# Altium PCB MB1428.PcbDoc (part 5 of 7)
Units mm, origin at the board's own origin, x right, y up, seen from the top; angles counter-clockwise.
Board outline 55.88 x 152.4 mm, 4 copper layers (Top Layer, Signal Layer 1, Signal Layer 2, Bottom Layer), stack 1.614 mm thick; 396 components, 227 nets, 1346 pads, 1469 vias.
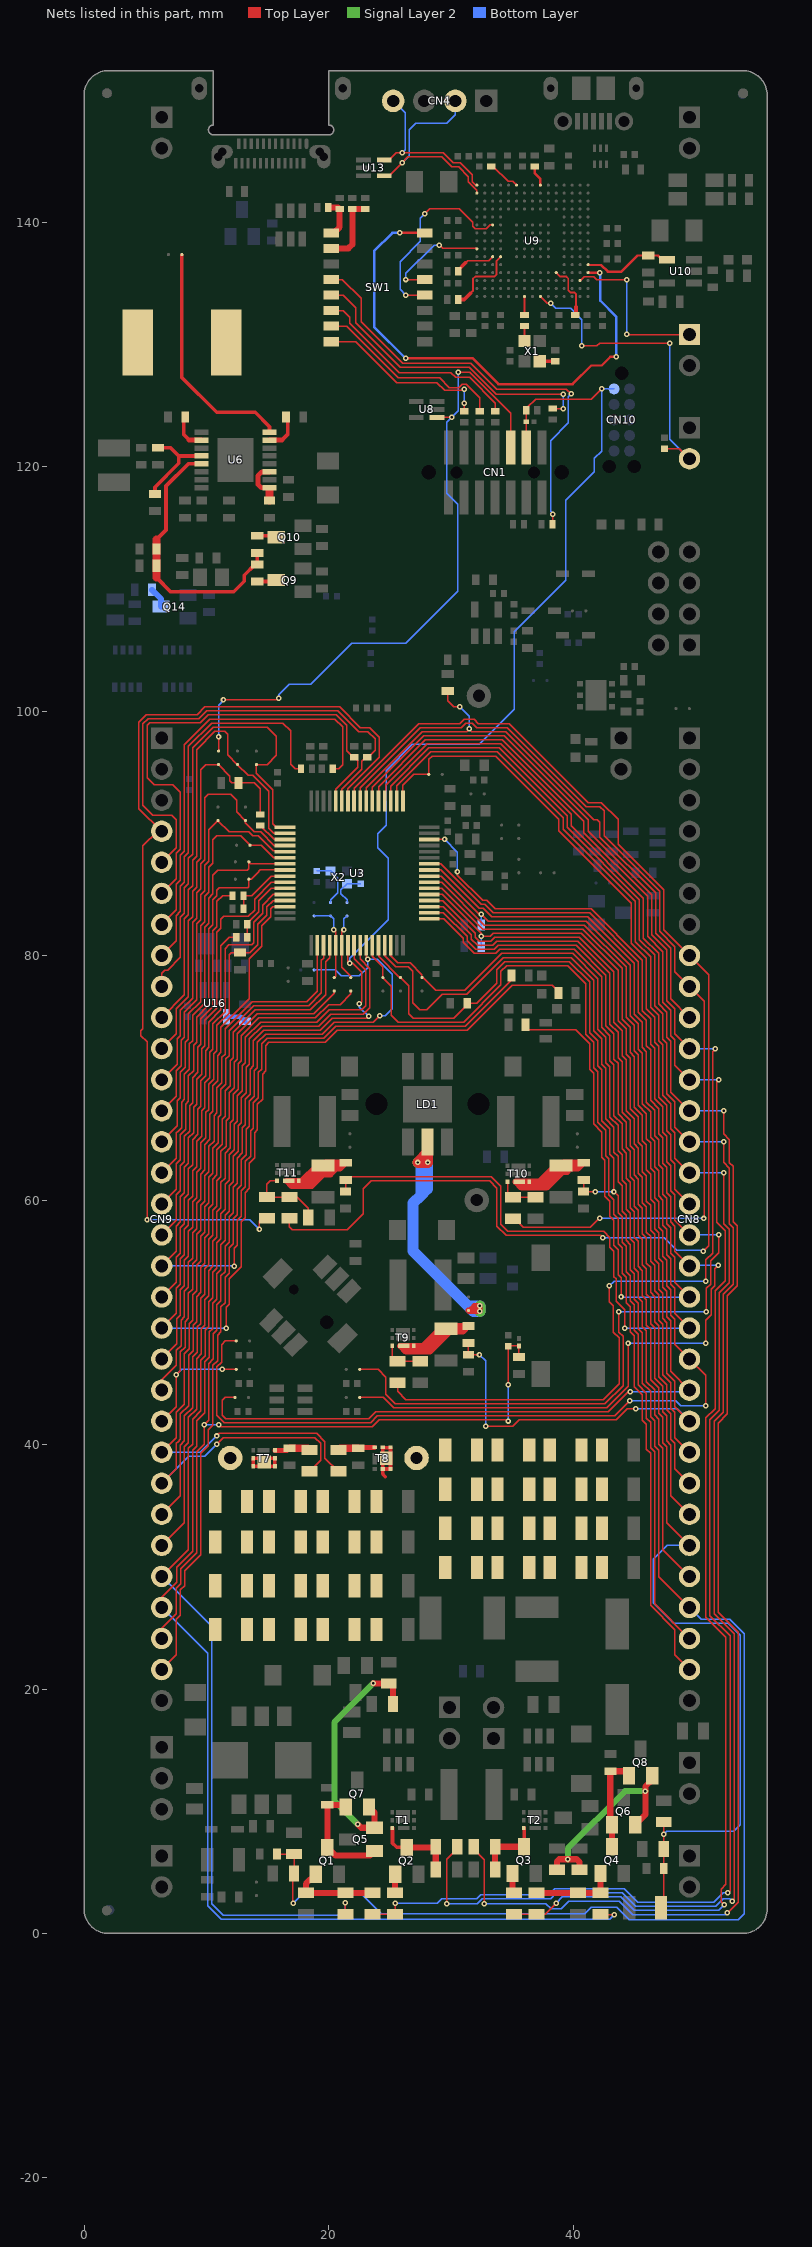
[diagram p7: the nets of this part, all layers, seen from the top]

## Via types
v1: diameter 0.45, hole 0.2, Top Layer to Bottom Layer, tented both sides, 1460 vias
v2: diameter 0.6, hole 0.2, Top Layer to Bottom Layer, tented both sides, 9 vias

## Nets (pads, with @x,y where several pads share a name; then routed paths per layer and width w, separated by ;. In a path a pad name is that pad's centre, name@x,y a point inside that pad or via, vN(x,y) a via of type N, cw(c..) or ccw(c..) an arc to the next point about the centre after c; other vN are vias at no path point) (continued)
NetQ1_1: Q1.1 R1.2 R2.2 R3.2 | length 7.3
  Top Layer w0.5: Q1.1@18.95,4.85 18.15,4.05 R1.2@18.15,3.325 R2.2@21.375,3.325 R3.2@23.6,3.325
NetQ1_3: Q1.3 Q5.1 Q7.1 R23.1 | length 9.3
  Top Layer w0.5: Q7.1@21.4,10.35 21.225,10.525 R23.1@19.9,10.525 Q1.3@19.9,7.05 20.575,6.375 23.375,6.375 Q5.1@23.75,6.75
NetQ2_1: Q2.1 R4.2 | length 1.5
  Top Layer w0.5: R4.2@25.45,3.325 Q2.1@25.45,4.85
NetQ2_3: Q2.3 R12.2 R19.2 T1.3 | length 6.8
  Top Layer w0.3: T1.3@25.238,8.625 25.238,7.387 25.575,7.05 Q2.3@26.4,7.05
  Top Layer w0.5: Q2.3@26.4,7.05 28.725,7.05 R19.2@28.775,7.1 R12.2@28.775,5.25
NetQ3_1: Q3.1 R5.1 | length 1.6
  Top Layer w0.5: Q3.1@35.05,4.9 35.05,3.45 R5.1@35.175,3.325
NetQ3_3: Q3.3 R13.2 R20.1 T2.3 | length 5.7
  Top Layer w0.3: Q3.3@36,7.1 T2.3@36,8.625
  Top Layer w0.5: R13.2@33.625,5.25 R20.1@33.625,7.1 Q3.3@36,7.1
NetQ4_1: Q4.1 R6.1 R7.2 R8.1 | length 6.8
  Top Layer w0.5: R6.1@37.025,3.325 R7.2@40.4,3.325 R8.1@42.25,3.325 Q4.1@42.25,4.9
NetQ4_3: Q4.3 Q6.1 Q8.1 R26.1 | length 7.9
  Top Layer w0.5: Q4.3@43.2,7.1 Q6.1@43.2,8.9 43.05,9.05 43.05,13.25 R26.1@43.075,13.275 44.2,13.275 Q8.1@44.575,12.9
NetQ5_2: Q5.2 Q7.2 R27.1 R28.1 | length 20.1
  Top Layer w0.5: v1(22.4,8.925) 22.675,8.65 Q5.2@23.75,8.65 23.75,9.9 Q7.2@23.3,10.35 ; v1(23.675,20.475) 23.7,20.45 R28.1@24.925,20.45 25.275,20.1 R27.1@25.275,18.775
  Signal Layer 2 w0.5: v1(22.4,8.925) 20.475,10.85 20.475,17.275 v1(23.675,20.475)
NetQ6_2: Q6.2 Q8.2 R14.2 R15.2 | length 17.1
  Top Layer w0.5: R14.2@38.675,5.2 38.675,5.875 38.875,6.075 v1(39.588,6.075) 40.3,6.075 40.525,5.85 R15.2@40.525,5.2 ; Q6.2@45.1,8.9 45.925,9.725 v1(45.925,11.65) 45.925,12.025 46.475,12.575 Q8.2@46.475,12.9
  Signal Layer 2 w0.5: v1(39.588,6.075) 39.588,6.962 44.275,11.65 v1(45.925,11.65)
NetQ9_3: Q9.3 R99.1 | length 1.6
  Top Layer w0.3: R99.1@14.175,110.6 15.6,110.6 Q9.3@15.725,110.725
NetQ10_3: Q10.3 R102.1 | length 1.6
  Top Layer w0.3: R102.1@14.175,114.35 15.6,114.35 Q10.3@15.725,114.225
NetQ14_3: Q14.3 R142.1 | length 1.7
  Bottom Layer w0.5: R142.1@5.55,109.925 6.3,109.175 Q14.3@6.3,108.55
NetR29_1: R29.1 R33.1 R41.1 R49.1 T7.1 T7.2 T7.5 T7.6 T7.8 TP1.1 | length 4.8
  Top Layer w0.3: T7.6@13.85,38.225 15.6,38.225 15.6,38.875 T7.5@13.85,38.875 T7.6@13.85,38.225
NetR29_2: R29.2 R30.1 R33.2 R34.1 R41.2 R42.1 R49.2 R50.1
NetR30_2: R30.2 R31.1 R34.2 R35.1 R42.2 R43.1 R50.2 R51.1
NetR31_2: R31.2 R32.1 R35.2 R36.1 R43.2 R44.1 R51.2 R52.1
NetR37_1: R37.1 R45.1 R53.1 R61.1 T8.1 T8.2 T8.5 T8.6 T8.8 TP2.1 | length 5.5
  Top Layer w0.3: 24.65,37.375 24.425,37.6 T8.5@24.425,38 ; T8.5@24.425,38 24.425,39.75 25.075,39.75 T8.6@25.075,38 T8.5@24.425,38
NetR37_2: R37.2 R38.1 R45.2 R46.1 R53.2 R54.1 R61.2 R62.1
NetR38_2: R38.2 R39.1 R46.2 R47.1 R54.2 R55.1 R62.2 R63.1
NetR39_2: R39.2 R40.1 R47.2 R48.1 R55.2 R56.1 R63.2 R64.1
NetR57_2: R57.2 R59.2 T7.3 | length 3
  Top Layer w0.4: T7.3@15.6,39.525 16.625,39.525 R59.2@16.8,39.7
  Top Layer w0.6: R59.2@16.8,39.7 18.3,39.7 R57.2@18.45,39.55
NetR58_2: R58.2 R60.2 T8.3 | length 3.1
  Top Layer w0.4: R60.2@22.425,39.7 22.475,39.75 T8.3@23.775,39.75
  Top Layer w0.6: R58.2@20.8,39.55 20.95,39.7 R60.2@22.425,39.7
NetR65_2: R65.2 R66.2 T9.3 | length 3.3
  Top Layer w0.12: T9.3@25.225,48.075 25.225,47.225 R65.2@25.65,46.8 R66.2@27.5,46.8
NetR68_2: R68.2 R69.1 T9.4 T9.7 | length 16.4
  Top Layer w0.5: 27.9,47.6 28.298,47.6 29.825,49.127 R68.2@29.825,49.26 ; 27.9,47.6 29.6,49.3 R68.2@29.6,49.475 ; 27.9,47.6 26.325,47.6 25.85,48.075 T9.7@26.15,48.075 T9.4@26.975,48.075 27.75,48.075 29.15,49.475 R68.2@29.6,49.475 ; R68.2@29.6,49.475 29.815,49.26 R68.2@29.825,49.26 ; R68.2@29.6,49.475 R68.2@29.825,49.7 ; R68.2@29.825,49.26 R68.2@29.825,49.7 ; R68.2@29.825,49.26 31.01,49.26 R69.1@31.45,49.7 R68.2@29.825,49.7
NetR71_2: R71.2 R74.2 R75.2 T11.3 | length 6.5
  Top Layer w0.12: T11.3@15.813,61.575 15.25,61.575 14.95,61.275 R74.2@14.95,60.25 R75.2@16.8,60.25 17.425,60.25 18.35,59.325 R71.2@18.35,58.575
NetR72_2: R72.2 R73.2 T10.3 | length 3.3
  Top Layer w0.12: T10.3@34.67,61.5 34.67,60.65 R72.2@35.095,60.225 R73.2@36.945,60.225
NetR76_2: R76.2 R78.1 T10.4 T10.7 | length 17
  Top Layer w0.5: R76.2@39.23,62.67 R76.2@39.175,62.67 ; R76.2@39.245,62.375 R76.2@39.245,62.6 ; R76.2@39.3,62.6 40.42,62.6 R78.1@40.87,63.05 39.245,63.05 R76.2@39.02,62.825 ; 37.375,61.025 37.847,61.025 39.02,62.198 ; 37.375,61.025 R76.2@39.02,62.67 ; 37.375,61.025 35.775,61.025 35.3,61.5 T10.7@35.595,61.5 T10.4@36.42,61.5 37.225,61.5 38.55,62.825 R76.2@39.02,62.825 ; 39.02,62.198 R76.2@39.02,62.67 ; 39.02,62.198 39.142,62.32 39.525,62.32 R76.2@39.245,62.6 ; R76.2@39.02,62.67 R76.2@39.175,62.67 ; R76.2@39.02,62.67 R76.2@39.02,62.825 ; R76.2@39.02,62.825 R76.2@39.175,62.67 ; R76.2@39.175,62.67 R76.2@39.245,62.6
NetR77_2: R77.2 R79.1 T11.4 T11.7 | length 15.3
  Top Layer w0.5: 18.025,61.175 18.625,61.175 19.55,62.1 ; 18.025,61.175 R77.2@19.55,62.7 ; 18.025,61.175 16.962,61.175 16.562,61.575 T11.7@16.738,61.575 T11.4@17.562,61.575 17.825,61.575 19.075,62.825 R77.2@19.55,62.825 ; 19.55,62.1 R77.2@19.55,62.7 ; 19.55,62.1 20.15,62.1 20.65,62.6 ; R77.2@19.55,62.7 R77.2@19.55,62.825 ; R77.2@19.55,62.825 19.775,62.6 20.65,62.6 ; R77.2@19.55,62.825 19.775,63.05 R79.1@21.4,63.05 20.95,62.6 20.65,62.6
NetR84_1: R84.1 R85.1 U3.59 | length 6
  Top Layer w0.12: R84.1@13.35,81.5 R85.1@13.35,82.55 13.35,82.658 14.279,83.587 14.279,84.484 15.299,85.504 U3.59@16.439,85.504
NetR86_1: R86.1 R87.1 U3.57 | length 5.1
  Top Layer w0.12: R86.1@13.05,83.85 R87.1@13.05,84.9 13.725,84.9 15.329,86.504 U3.57@16.439,86.504
NetR88_2: R88.2 U3.51 | length 2.5
  Top Layer w0.12: R88.2@14.425,90.65 14.425,90.63 15.551,89.504 U3.51@16.439,89.504
NetR105_1: R105.1 SW1.4 | length 36.2
  Top Layer w0.12: SW1.4@20.16,135.31 SW1.4@20.24,135.31 21.14,135.31 22.685,133.765 22.685,131.84 26.055,128.47 31.635,128.47 33.755,126.35 39.455,126.35 v1(39.855,125.95) ; R105.1@38.325,115.282 38.355,115.312 v1(38.355,116.125)
  Bottom Layer w0.12: v1(38.355,116.125) 38.355,116.15 38.162,116.343 38.162,122.132 39.63,123.6 39.63,125.725 v1(39.855,125.95)
NetR111_1: R111.1 SW1.8 | length 14.4
  Top Layer w0.12: SW1.8@20.205,130.23 SW1.8@20.24,130.23 22.245,130.23 25.6,126.875 28.862,126.875 29.505,126.232 30.987,126.232 v1(31.105,126.35) ; R111.1@31.1,124.532 31.1,125.195 v1(31.105,125.2)
  Bottom Layer w0.12: v1(31.105,125.2) v1(31.105,126.35)
NetR112_1: R112.1 SW1.7 | length 16
  Top Layer w0.12: SW1.7@20.2,131.5 SW1.7@20.24,131.5 21.475,131.5 25.7,127.275 29.08,127.275 29.883,126.472 30.654,126.472 30.937,126.755 31.273,126.755 32.375,125.653 R112.1@32.375,124.532
NetR113_1: R113.1 SW1.6 | length 17.5
  Top Layer w0.12: SW1.6@20.195,132.77 SW1.6@20.24,132.77 21.205,132.77 21.75,132.225 21.75,131.75 25.8,127.7 30,127.7 30.396,127.304 31.546,127.304 33.65,125.2 R113.1@33.65,124.532
NetR114_1: R114.1 SW1.5 | length 25.1
  Top Layer w0.12: SW1.5@20.235,134.04 SW1.5@20.24,134.04 21.185,134.04 22.225,133 22.225,131.775 25.871,128.129 31.521,128.129 33.725,125.925 39.02,125.925 v1(39.205,125.924) ; R114.1@38.33,124.75 v1(39.205,124.75)
  Bottom Layer w0.12: v1(39.205,124.75) v1(39.205,125.924)
NetR116_2: R116.2 X1.1 | length 1.3
  Top Layer w0.3: X1.1@37.28,128.625 R116.2@38.53,128.625
NetR117_1: R117.1 X1.3 | length 1.2
  Top Layer w0.15: X1.3@36.03,130.275 R117.1@36.03,131.5
NetR118_2: R118.2 U9.L4 | length 4.7
  Top Layer w0.15: U9.L4@38.63,135.875 38.96,135.545 39.46,135.545 39.61,135.395 39.61,134.42 39.775,134.255 40.1,134.255 40.25,134.105 40.25,133.08
  Top Layer w0.3: R118.2@40.18,132.4 40.25,132.47 40.25,133.08
NetR120_2: R120.2 U9.D6 | length 6.1
  Top Layer w0.15: 31.63,134.2 31.81,134.38 31.81,135.358 32.002,135.55 33.558,135.55 33.75,135.742 33.75,136.845 U9.D6@34.08,137.175
  Top Layer w0.3: R120.2@30.605,133.675 31.105,133.675 31.63,134.2
NetR123_2: R123.2 U9.C6 | length 3.4
  Top Layer w0.15: 31.205,136.675 31.375,136.845 33.1,136.845 U9.C6@33.43,137.175
  Top Layer w0.3: R123.2@30.605,135.975 30.605,136.075 31.205,136.675
NetR124_2: R124.2 R125.2 SW1.1 | length 3.4
  Top Layer w0.5: R124.2@19.975,141.2 20.78,141.2 R125.2@20.905,141.075 20.905,139.6 20.425,139.12 SW1.1@20.24,139.12 SW1.1@20.155,139.12
NetR126_1: R126.1 R127.1 SW1.2 | length 5.9
  Top Layer w0.5: SW1.2@20.15,137.85 SW1.2@20.24,137.85 21.63,137.85 21.955,138.175 R126.1@21.955,141.075 R127.1@23.005,141.075
NetR131_2: R131.2 U9.J15 | length 1.7
  Top Layer w0.2: R131.2@36.855,144.525 36.855,144.023 37.33,143.548 U9.J15@37.33,143.025
NetR134_1: R134.1 U16.4 | length 1.7
  Bottom Layer w0.4: U16.4@11.65,75 12.8,75 R134.1@13.175,74.625
NetSB10_2: SB10.2 SB35.2 SB36.2 U3.5 | length 6.6
  Top Layer w0.12: v1(20.414,82.129) 20.589,81.954 U3.5@20.589,80.854 20.589,78.329 SB10.2@20.464,78.204
  Bottom Layer w0.12: SB36.2@18.814,83.254 SB35.2@20.164,83.254 20.414,83.004 v1(20.414,82.129)
NetSB11_2: SB11.2 SB34.2 U3.6 | length 5.6
  Top Layer w0.12: v1(21.264,82.129) 21.264,82.154 21.089,81.979 U3.6@21.089,80.854 21.089,79.029 21.814,78.304 SB11.2@21.814,78.204
  Bottom Layer w0.12: v1(21.264,82.129) 21.264,83.004 SB34.2@21.514,83.254
NetSB32_2: SB32.2 U6.16 | length 19.3
  Top Layer w0.3: SB32.2@8,137.35 8,127.3 10.85,124.45 14,124.45 15.175,123.275 U6.16@15.175,122.825
NRST: C56.2 JP6.2 U9.J1 | length 25.9
  Top Layer w0.12: U9.J1@37.33,133.925 37.88,133.375 v1(38.18,133.375) ; v1(40.725,129.875) 41.95,129.875 42.175,130.1 v1(47.93,130.1) ; C56.2@47.475,121.475 48.7,121.475 JP6.2@49.525,120.65
  Bottom Layer w0.12: v1(38.18,133.375) 38.605,132.95 39.8,132.95 40.73,132.02 40.73,130.1 ; v1(47.93,130.1) 47.93,122.245 JP6.2@49.525,120.65
OSC_IN: C93.2 SB35.1 X2.1 | length 4.2
  Bottom Layer w0.12: C93.2@19.039,86.929 X2.1@20.164,86.929 20.169,86.929 20.769,86.329 20.769,85.159 20.164,84.554 SB35.1@20.164,84.354
OSC_IN_STLK: R117.2 U9.G1 | length 1.5
  Top Layer w0.15: R117.2@36.03,132.4 U9.G1@36.03,133.925
OSC_OUT: C92.2 SB34.1 X2.3 | length 3.1
  Bottom Layer w0.12: SB34.1@21.514,84.354 21.514,84.555 21.009,85.06 21.009,85.374 X2.3@21.514,85.879 C92.2@22.639,85.879
PA0: C18.2 C22.2 CN8.30 R78.2 SB13.2 U3.12 | length 85.5
  Top Layer w0.12: U3.12@24.089,80.854 24.089,79.929 25.814,78.204 SB13.2@25.889,78.204 26.569,77.524 26.569,75.256 26.935,74.89 30.24,74.89 31.35,76 C22.2@31.35,76.1 32.13,76.1 33.768,77.738 33.768,78.842 34.435,79.509 39.702,79.509 41.361,77.85 41.361,73.709 42.025,73.045 42.025,70.974 42.357,70.642 42.357,66.501 43.021,65.837 43.021,63.767 43.353,63.435 v1(43.353,60.678) 43.685,60.346 43.685,58.962 44.017,58.63 44.017,56.559 44.349,56.227 44.349,54.157 44.681,53.825 44.681,51.754 45.013,51.422 45.013,49.352 45.345,49.02 45.345,44.879 46.009,44.215 46.009,42.144 46.341,41.812 46.341,39.742 46.673,39.41 46.673,26.987 CN8.30@49.53,24.13 ; R78.2@40.87,61.65 C18.2@40.87,60.7 40.895,60.675 v1(41.825,60.675)
  Bottom Layer w0.12: v1(41.825,60.675) 41.828,60.678 v1(43.353,60.678)
PA1: C3.2 CN8.29 R11.2 R17.1 U3.13 | length 151.1
  Top Layer w0.12: C3.2@15.775,6.5 R17.1@17.175,6.5 R11.2@17.175,4.9 17.075,4.8 17.075,2.5 v1(17.1,2.475) ; U3.13@24.589,80.854 24.589,79.969 25.479,79.079 26.539,79.079 26.901,78.717 26.901,76.144 27.471,75.574 28.024,75.574 29.293,76.843 31.299,76.843 34.297,79.841 39.839,79.841 41.693,77.987 41.693,73.846 42.357,73.182 42.357,71.112 42.689,70.78 42.689,66.639 43.353,65.975 43.353,63.904 43.685,63.572 43.685,61.502 44.017,61.17 44.017,59.099 44.349,58.767 44.349,56.697 44.681,56.365 44.681,54.294 45.013,53.962 45.013,51.892 45.345,51.56 45.345,49.489 45.677,49.157 45.677,45.016 46.341,44.352 46.341,42.282 46.673,41.95 46.673,39.879 47.005,39.547 47.005,29.195 CN8.29@49.53,26.67
  Bottom Layer w0.12: v1(17.1,2.475) 18.1,3.475 22.475,3.475 24.325,1.625 40.95,1.625 41.475,2.15 43.575,2.15 44.603,1.122 53.522,1.122 54,1.6 54,24.538 52.831,25.707 50.493,25.707 CN8.29@49.53,26.67
PA2: CN8.28 SB14.2 U3.14 | length 73.3
  Top Layer w0.12: U3.14@25.089,80.854 25.089,79.969 25.647,79.411 26.676,79.411 27.639,78.449 SB14.2@27.639,78.304 ; SB14.2@27.639,78.204 SB14.2@27.639,78.304 ; CN8.28@49.53,29.21 47.337,31.403 47.337,39.685 47.005,40.017 47.005,42.087 46.673,42.419 46.673,44.49 46.009,45.154 46.009,49.295 45.677,49.627 45.677,51.697 45.345,52.029 45.345,54.1 45.013,54.432 45.013,56.502 44.681,56.834 44.681,58.905 44.349,59.237 44.349,61.307 44.017,61.639 44.017,63.71 43.685,64.042 43.685,66.112 43.021,66.776 43.021,70.917 42.689,71.249 42.689,73.32 42.025,73.984 42.025,78.125 39.977,80.173 34.16,80.173 31.162,77.175 28.768,77.175 SB14.2@27.639,78.304
PA3: C2.2 CN8.27 R9.2 R18.2 R22.1 U3.17 | length 110.4
  Top Layer w0.12: U3.17@28.239,83.004 29.427,83.004 31.004,81.427 31.004,81.082 31.912,80.174 33.691,80.174 34.022,80.505 40.114,80.505 42.357,78.262 42.357,74.121 43.021,73.457 43.021,71.387 43.353,71.055 43.353,66.914 44.017,66.25 44.017,64.179 44.349,63.847 44.349,61.777 44.681,61.445 44.681,59.374 45.013,59.042 45.013,56.972 45.345,56.64 45.345,54.569 45.677,54.237 45.677,52.167 46.009,51.835 46.009,49.764 46.341,49.432 46.341,45.291 47.005,44.627 47.005,42.557 47.337,42.225 47.337,40.154 47.669,39.822 47.669,33.611 CN8.27@49.53,31.75 ; R9.2@47.2,2.1 47.425,2.325 C2.2@47.425,5.325 R18.2@47.425,6.925 v1(47.425,8.125) R22.1@47.425,9.125
  Bottom Layer w0.12: v1(47.425,8.125) 47.675,8.375 53.143,8.375 53.668,8.9 53.668,24.4 52.693,25.375 48.25,25.375 46.575,27.05 46.575,30.625 47.7,31.75 CN8.27@49.53,31.75
PA4: CN8.26 U3.18 | length 64
  Top Layer w0.12: U3.18@28.239,83.504 29.397,83.504 31.336,81.565 31.336,81.22 32.05,80.506 33.554,80.506 33.885,80.837 40.252,80.837 42.689,78.4 42.689,74.259 43.353,73.595 43.353,71.524 43.685,71.192 43.685,67.051 44.349,66.387 44.349,64.317 44.681,63.985 44.681,61.914 45.013,61.582 45.013,59.512 45.345,59.18 45.345,57.109 45.677,56.777 45.677,54.707 46.009,54.375 46.009,52.304 46.341,51.972 46.341,49.902 46.673,49.57 46.673,45.429 47.337,44.765 47.337,42.694 47.669,42.362 47.669,40.292 48.001,39.96 48.001,35.819 CN8.26@49.53,34.29
PA5: CN8.25 U3.19 | length 61.9
  Top Layer w0.12: U3.19@28.239,84.004 29.366,84.004 31.668,81.702 31.668,81.357 32.187,80.838 33.416,80.838 33.747,81.169 40.389,81.169 43.021,78.537 43.021,74.396 43.685,73.732 43.685,71.662 44.017,71.33 44.017,67.189 44.681,66.525 44.681,64.454 45.013,64.122 45.013,62.052 45.345,61.72 45.345,59.649 45.677,59.317 45.677,57.247 46.009,56.915 46.009,54.844 46.341,54.512 46.341,52.442 46.673,52.11 46.673,50.039 47.005,49.707 47.005,45.566 47.669,44.902 47.669,42.832 48.001,42.5 48.001,40.429 48.333,40.097 48.333,38.027 CN8.25@49.53,36.83
PA6: CN8.24 U3.20 | length 59.9
  Top Layer w0.12: U3.20@28.239,84.504 29.336,84.504 32,81.84 32,81.495 32.325,81.17 33.279,81.17 33.61,81.501 40.527,81.501 43.353,78.675 43.353,74.534 44.017,73.87 44.017,71.799 44.349,71.467 44.349,67.326 45.013,66.662 45.013,64.592 45.345,64.26 45.345,62.189 45.677,61.857 45.677,59.787 46.009,59.455 46.009,57.384 46.341,57.052 46.341,54.982 46.673,54.65 46.673,52.579 47.005,52.247 47.005,50.177 47.337,49.845 47.337,45.704 48.001,45.04 48.001,42.969 48.333,42.637 48.333,40.567 CN8.24@49.53,39.37
PA7: C14.2 C90.2 CN8.23 R69.2 U3.21 | length 84.1
  Top Layer w0.12: U3.21@28.239,85.004 29.305,85.004 32.5,81.809 v1(32.5,81.575) 33.214,81.575 33.472,81.833 40.664,81.833 43.685,78.812 43.685,74.671 44.349,74.007 44.349,71.937 44.681,71.605 44.681,67.464 45.345,66.8 45.345,64.729 45.677,64.397 45.677,62.327 46.009,61.995 46.009,59.924 46.341,59.592 46.341,57.522 46.673,57.19 46.673,55.119 47.005,54.787 47.005,52.717 47.337,52.385 47.337,50.314 47.669,49.982 47.669,45.841 48.333,45.177 48.333,43.107 CN8.23@49.53,41.91 ; R69.2@31.45,48.3 C14.2@31.45,47.35 v1(32.35,47.35) ; v1@32.85,41.5 v1(32.875,41.5) 35.075,41.5 35.59,42.015 43.535,42.015 44.445,42.925 v1(45.125,42.925)
  Bottom Layer w0.12: v1(32.35,47.35) 32.85,46.85 v1@32.85,41.5 ; C90.2@32.5,80.75 v1(32.5,81.575) ; v1(45.125,42.925) 48.515,42.925 CN8.23@49.53,41.91
PA8: CN9.4 R74.1 U3.42 | length 80.9
  Top Layer w0.12: v1(5.15,58.4) 5.15,72.95 4.65,73.45 4.65,73.854 4.821,74.025 4.821,88.975 6.016,90.17 CN9.4@6.35,90.17 4.489,92.031 4.489,99.103 5.1,99.714 9.247,99.714 9.883,100.35 20.909,100.35 22.61,98.649 23.361,98.649 24.146,97.864 24.146,96.217 21.589,93.66 U3.42@21.589,92.654 ; v1(14.35,57.6) 14.35,58.25 14.6,58.5 R74.1@14.95,58.5
  Bottom Layer w0.12: v1(5.15,58.4) 13.55,58.4 v1(14.35,57.6)
PA9: CN9.5 R94.2 U3.43 | length 40.6
  Top Layer w0.12: CN9.5@6.35,87.63 7.547,88.827 7.547,91.128 7.175,91.5 5.625,91.5 4.821,92.304 4.821,98.965 5.238,99.382 9.384,99.382 10.02,100.018 20.771,100.018 22.472,98.317 23.224,98.317 23.814,97.727 23.814,96.785 23.627,96.598 23.623,96.598 23.254,96.229 23.039,96.229 22.722,95.912 22.722,95.263 21.089,93.63 U3.43@21.089,92.654
PA10: CN9.6 R93.2 U3.44 | length 40.8
  Top Layer w0.12: CN9.6@6.35,85.09 7.547,86.287 7.547,88.357 7.879,88.689 7.879,93.371 7.275,93.975 5.725,93.975 5.153,94.547 5.153,98.828 5.375,99.05 9.522,99.05 10.158,99.686 20.634,99.686 21.478,98.842 21.478,96.757 22.01,96.225 R93.2@22.1,96.225 22.39,95.935 22.39,95.4 20.589,93.599 U3.44@20.589,92.654
PA11: CN9.7 R91.1 | length 33.6
  Top Layer w0.12: CN9.7@6.35,82.55 7.547,83.747 7.547,85.817 7.879,86.149 7.879,88.22 8.211,88.552 8.211,97.27 10.295,99.354 20.496,99.354 21.146,98.704 21.146,95.611 20.839,95.304 R91.1@20.339,95.304
PA12: CN9.8 R90.1 | length 31.1
  Top Layer w0.12: CN9.8@6.35,80.01 7.547,81.207 7.547,83.277 7.879,83.609 7.879,85.68 8.211,86.012 8.211,88.082 8.543,88.414 8.543,97.132 10.433,99.022 16.271,99.022 16.914,98.379 16.914,95.654 17.264,95.304 R90.1@17.739,95.304
PA13: CN9.9 SB29.2 U3.49 | length 38.6
  Top Layer w0.12: CN9.9@6.35,77.47 6.35,78.563 6.6,78.813 6.846,78.813 7.879,79.846 7.879,83.14 8.211,83.472 8.211,85.542 8.543,85.874 8.543,87.945 8.875,88.277 8.875,96.995 10.57,98.69 14.985,98.69 15.725,97.95 15.725,96.375 14.975,95.625 SB29.2@14.1,95.625 14.1,94.9 15.432,93.568 15.432,90.775 15.703,90.504 U3.49@16.439,90.504
PA14: CN9.10 SB27.2 U3.50 | length 37.2
  Top Layer w0.12: CN9.10@6.35,74.93 8.211,76.791 8.211,83.002 8.543,83.334 8.543,85.4 8.875,85.732 8.875,87.807 9.207,88.139 9.207,96.857 10.708,98.358 11.5,98.358 11.75,98.108 11.75,96.425 SB27.2@12.55,95.625 13.425,94.75 13.78,94.75 15.1,93.43 15.1,90.425 15.521,90.004 U3.50@16.439,90.004
PA15: CN9.11 R88.1 R89.1 SB28.2 | length 32.3
  Top Layer w0.12: CN9.11@6.35,72.39 7.547,73.587 7.547,75.657 8.543,76.653 8.543,82.865 8.875,83.197 8.875,85.262 9.207,85.594 9.207,87.65 9.539,87.982 9.539,95.189 9.975,95.625 SB28.2@11,95.625 11,95.605 11.925,94.68 11.925,94.3 12.1,94.125 R89.1@12.625,94.125 13.936,94.125 14.425,93.636 R88.1@14.425,91.55
PB0: C19.2 C91.2 CN8.20 R79.2 U3.24 | length 91.8
  Top Layer w0.12: C19.2@21.4,60.7 R79.2@21.4,61.65 21.657,61.907 33.318,61.907 34.107,61.118 34.107,58.003 34.664,57.446 42.5,57.446 43.021,56.925 43.021,56.147 43.353,55.815 43.353,53.744 43.522,53.575 43.522,51.728 44.225,51.025 v1(44.225,49.525) ; U3.24@28.239,86.504 29.214,86.504 32.343,83.375 v1(32.5,83.375) 33.046,82.829 41.077,82.829 44.681,79.225 44.681,75.084 45.345,74.42 45.345,72.349 45.677,72.017 45.677,67.876 46.341,67.212 46.341,65.142 46.673,64.81 46.673,62.739 47.005,62.407 47.005,60.337 47.337,60.005 47.337,57.934 47.669,57.602 47.669,55.532 48.001,55.2 48.001,53.129 48.333,52.797 48.333,50.727 CN8.20@49.53,49.53
  Bottom Layer w0.12: C91.2@32.5,82.5 v1(32.5,83.375) ; v1(44.225,49.525) 44.23,49.53 CN8.20@49.53,49.53
PB1: CN8.19 R80.2 U3.25 | length 82.5
  Top Layer w0.12: U3.25@28.239,87.004 29.198,87.004 32.339,83.863 32.65,83.863 33.352,83.161 41.214,83.161 45.013,79.362 45.013,75.221 45.677,74.557 45.677,72.487 46.009,72.155 46.009,68.014 46.673,67.35 46.673,65.279 47.005,64.947 47.005,62.877 47.337,62.545 47.337,60.474 47.669,60.142 47.669,58.072 48.001,57.74 48.001,55.669 48.333,55.337 48.333,53.267 CN8.19@49.53,52.07 ; R80.2@36.125,74.35 36.125,74.15 36.35,73.925 40.206,73.925 41.361,72.77 41.361,70.699 41.693,70.367 41.693,66.226 42.357,65.562 42.357,63.492 42.593,63.256 42.593,60.312 43.021,59.884 43.021,58.687 43.353,58.355 43.353,56.284 43.685,55.952 43.685,53.882 43.927,53.64 v1(43.927,52.078)
  Bottom Layer w0.12: v1(43.927,52.078) 43.935,52.07 CN8.19@49.53,52.07
PB2: CN8.18 SB3.2 U3.26 | length 89.1
  Top Layer w0.12: SB3.2@22.55,43.85 24.48,43.85 25.319,43.011 42.75,43.011 44.5,44.761 v1(44.5,48.275) ; U3.26@28.239,87.504 29.168,87.504 32.477,84.195 32.788,84.195 33.49,83.493 41.352,83.493 45.345,79.5 45.345,75.359 46.009,74.695 46.009,72.624 46.341,72.292 46.341,68.151 47.005,67.487 47.005,65.417 47.337,65.085 47.337,63.014 47.669,62.682 47.669,60.612 48.001,60.28 48.001,58.209 48.333,57.877 48.333,55.807 CN8.18@49.53,54.61 ; v1(50.85,48.275) 50.85,50.15 51.305,50.605 51.305,52.71 51.587,52.992 51.587,54.362 v1(51.875,54.65)
  Bottom Layer w0.12: v1(44.5,48.275) v1(50.85,48.275) ; CN8.18@49.53,54.61 49.57,54.65 v1(51.875,54.65)
PB3: CN9.16 SB16.1 U3.56 | length 34.1
  Top Layer w0.12: CN9.16@6.35,59.69 7.547,60.887 7.547,62.957 7.879,63.289 7.879,65.359 8.306,65.787 8.306,67.858 8.543,68.094 8.543,70.165 8.955,70.577 8.955,72.648 9.207,72.899 9.207,74.97 10.203,75.966 10.203,82.177 10.535,82.509 10.535,84.575 10.867,84.907 10.867,85.35 11.067,85.55 13.375,85.55 13.475,85.65 SB16.1@13.475,86.25 13.675,86.25 14.175,86.75 14.429,87.004 U3.56@16.439,87.004
PB4: CN9.17 R87.2 | length 30.6
  Top Layer w0.12: CN9.17@6.35,57.15 7.547,58.347 7.547,60.417 7.879,60.749 7.879,62.82 8.211,63.152 8.211,65.222 8.638,65.649 8.638,67.72 8.875,67.957 8.875,70.027 9.287,70.44 9.287,72.51 9.539,72.762 9.539,74.832 10.535,75.828 10.535,82.04 10.867,82.372 10.867,84.437 11.33,84.9 R87.2@12.15,84.9
PB5: CN9.18 R82.2 U3.58 | length 85.4
  Top Layer w0.12: CN9.18@6.35,54.61 7.547,55.807 7.547,57.877 7.879,58.209 7.879,60.275 8.211,60.607 8.211,62.682 8.543,63.014 8.543,65.084 8.97,65.512 8.97,67.583 9.207,67.819 9.207,69.89 9.619,70.302 9.619,72.373 9.871,72.624 9.871,74.695 10.867,75.691 10.867,81.902 11.199,82.234 11.199,82.974 11.425,83.2 13.422,83.2 13.947,83.725 13.947,84.622 15.329,86.004 U3.58@16.439,86.004 ; v1(12.3,54.6) 12.3,56.057 12.527,56.284 12.527,58.35 12.859,58.682 12.859,60.757 13.191,61.089 13.191,63.159 13.618,63.586 13.618,65.657 13.855,65.894 13.855,67.965 14.267,68.377 14.267,70.447 14.519,70.699 14.519,72.77 14.986,73.237 19.604,73.237 20.593,74.226 31.196,74.226 34.975,78.005 R82.2@34.975,78.375
  Bottom Layer w0.12: CN9.18@6.35,54.61 12.29,54.61 v1(12.3,54.6)
PB6: CN9.19 R84.2 | length 32.3
  Top Layer w0.12: CN9.19@6.35,52.07 7.547,53.267 7.547,55.337 7.879,55.669 7.879,57.74 8.211,58.072 8.211,60.137 8.543,60.469 8.543,62.545 8.875,62.877 8.875,64.947 9.302,65.374 9.302,67.445 9.539,67.682 9.539,69.752 9.951,70.165 9.951,72.235 10.203,72.487 10.203,74.557 11.199,75.553 11.199,80.824 11.875,81.5 R84.2@12.45,81.5
PB7: CN9.20 R81.2 U3.60 | length 97.4
  Top Layer w0.12: CN9.20@6.35,49.53 7.547,50.727 7.547,52.797 7.879,53.129 7.879,55.2 8.211,55.532 8.211,57.602 8.543,57.934 8.543,60 8.875,60.332 8.875,62.407 9.207,62.739 9.207,64.809 9.634,65.237 9.634,67.308 9.871,67.544 9.871,69.615 10.283,70.027 10.283,72.098 10.535,72.349 10.535,74.42 11.531,75.416 11.531,80.581 11.825,80.875 13.715,80.875 13.877,81.037 13.877,82.716 14.611,83.45 14.611,84.125 15.49,85.004 U3.60@16.439,85.004 ; v1(11.63,49.53) 11.63,51.246 11.863,51.479 11.863,53.55 12.859,54.546 12.859,58.212 13.191,58.544 13.191,60.62 13.523,60.952 13.523,63.022 13.95,63.449 13.95,65.52 14.187,65.757 14.187,67.827 14.599,68.239 14.599,70.31 14.851,70.562 14.851,72.632 15.124,72.905 19.742,72.905 20.731,73.894 31.333,73.894 35.014,77.575 38.3,77.575 38.8,77.075 R81.2@38.8,76.95
  Bottom Layer w0.12: CN9.20@6.35,49.53 v1(11.63,49.53)
PB8: CN9.21 R83.2 U3.61 | length 43.2
  Top Layer w0.12: CN9.21@6.35,46.99 7.6,48.24 7.6,50.31 7.879,50.589 7.879,52.66 8.211,52.992 8.211,55.062 8.543,55.394 8.543,57.465 8.875,57.797 8.875,59.862 9.207,60.194 9.207,62.27 9.539,62.602 9.539,64.672 9.966,65.099 9.966,67.17 10.203,67.407 10.203,69.477 10.615,69.89 10.615,71.96 10.867,72.212 10.867,74.282 11.863,75.278 11.863,80.075 12.038,80.25 R83.2@12.75,80.25 13.559,80.25 14.209,80.9 14.209,82.578 14.943,83.312 14.943,83.988 15.459,84.504 U3.61@16.439,84.504
PB9: CN9.22 U3.62 | length 44.3
  Top Layer w0.12: CN9.22@6.35,44.45 6.35,45.297 7.55,46.497 7.55,47.72 7.932,48.102 7.932,50.173 8.211,50.452 8.211,52.522 8.543,52.854 8.543,54.925 8.875,55.257 8.875,57.327 9.207,57.659 9.207,59.725 9.539,60.057 9.539,62.132 9.871,62.464 9.871,64.534 10.298,64.962 10.298,67.033 10.535,67.269 10.535,69.34 10.947,69.752 10.947,71.823 11.199,72.074 11.199,74.145 13.522,76.468 13.522,79.743 14.541,80.762 14.541,82.441 15.275,83.175 15.275,83.85 15.429,84.004 U3.62@16.439,84.004
PB10: CN8.17 SB4.2 U3.30 | length 93.3
  Top Layer w0.12: SB4.2@22.55,46.15 24.05,46.15 24.675,45.525 24.675,44.125 25.457,43.343 42.613,43.343 44.095,44.825 44.095,48.861 43.75,49.206 v1(43.75,50.85) ; U3.30@28.239,89.504 v1(29.489,89.504) ; v1(30.55,86.85) 30.55,86.591 32.614,84.527 32.925,84.527 33.627,83.825 41.489,83.825 45.677,79.637 45.677,75.496 46.341,74.832 46.341,72.762 46.673,72.43 46.673,68.289 47.337,67.625 47.337,65.554 47.669,65.222 47.669,63.152 48.001,62.82 48.001,60.749 48.333,60.417 48.333,58.347 CN8.17@49.53,57.15 ; v1(50.9,50.85) 50.9,52.775 51.255,53.13 51.255,55.035 51.925,55.705 v1(51.925,57.15)
  Bottom Layer w0.12: v1(29.489,89.504) 30.55,88.443 v1(30.55,86.85) ; v1(43.75,50.85) v1(50.9,50.85) ; CN8.17@49.53,57.15 v1(51.925,57.15)
PB11: CN8.16 SB26.1 U3.33 | length 53.8
  Top Layer w0.12: U3.33@26.089,92.654 26.089,93.934 26.979,94.825 SB26.1@28.2,94.825 28.2,96.046 28.48,96.326 33.675,96.326 38.854,91.147 38.854,90.212 44.769,84.297 44.769,81.015 46.009,79.775 46.009,75.634 46.673,74.97 46.673,72.899 47.005,72.567 47.005,68.426 47.669,67.762 47.669,65.692 48.001,65.36 48.001,63.289 48.333,62.957 48.333,60.887 CN8.16@49.53,59.69
PB12: CN8.15 R3.1 R4.1 U3.34 | length 146.1
  Top Layer w0.12: R3.1@23.6,1.575 R4.1@25.45,1.575 v1(25.45,2.475) ; U3.34@25.589,92.654 25.589,93.904 28.343,96.658 33.813,96.658 39.186,91.285 39.186,90.35 45.101,84.435 45.101,81.152 46.341,79.912 46.341,75.771 47.005,75.107 47.005,73.037 47.337,72.705 47.337,68.564 48.001,67.9 48.001,65.829 48.333,65.497 48.333,63.427 CN8.15@49.53,62.23 ; v1(52.325,62.225) 52.325,58.07 52.782,57.613 52.782,53.248 51.969,52.435 51.969,42.799 51.207,42.037 51.207,26.009 52.847,24.369 52.847,3.497 52.675,3.325 v1(52.65,3.325)
  Bottom Layer w0.12: v1(25.45,2.475) 28.89,2.475 29.27,2.855 32.113,2.855 32.445,3.187 38.042,3.187 38.505,3.65 44.178,3.65 45.282,2.546 51.529,2.546 52.308,3.325 v1(52.65,3.325) ; CN8.15@49.53,62.23 52.32,62.23 v1(52.325,62.225)
PB13: CN8.14 R19.1 U3.35 | length 146.2
  Top Layer w0.12: U3.35@25.089,92.654 25.089,93.874 28.205,96.99 33.95,96.99 39.518,91.422 39.518,90.487 45.433,84.572 45.433,81.29 46.673,80.05 46.673,75.909 47.337,75.245 47.337,73.174 47.669,72.842 47.669,68.701 48.333,68.037 48.333,65.967 CN8.14@49.53,64.77 ; v1(29.675,2.45) 29.675,6.075 30.525,6.925 R19.1@30.525,7.1 ; v1(52.325,64.765) 52.325,63.075 52.788,62.612 52.788,58.077 53.114,57.75 53.114,53.111 52.301,52.298 52.301,42.662 51.539,41.9 51.539,26.147 53.179,24.507 53.179,2.804 v1(53.025,2.65)
  Bottom Layer w0.12: v1(29.675,2.45) 32.177,2.45 32.582,2.855 38.18,2.855 38.643,3.318 44.041,3.318 45.145,2.214 51.666,2.214 52.302,2.85 52.825,2.85 v1(53.025,2.65) ; CN8.14@49.53,64.77 v1@52.32,64.77
PB14: CN8.13 R20.2 U3.36 | length 145
  Top Layer w0.12: U3.36@24.589,92.654 24.667,92.732 24.667,93.921 28.068,97.322 34.088,97.322 39.85,91.56 39.85,90.625 45.765,84.71 45.765,81.427 47.005,80.187 47.005,76.046 47.669,75.382 47.669,73.312 48.001,72.98 48.001,68.839 CN8.13@49.53,67.31 ; R20.2@31.875,7.1 31.875,6.925 32.75,6.05 v1(32.75,2.45) ; v1(52.325,67.305) 52.325,65.425 52.8,64.95 52.8,63.07 53.12,62.75 53.12,58.214 53.446,57.888 53.446,52.973 52.633,52.16 52.633,42.524 51.871,41.762 51.871,26.284 53.511,24.644 53.511,2.561 52.625,1.675 v1(52.625,1.7)
  Bottom Layer w0.12: v1(32.75,2.45) 37.775,2.45 38.2,2.025 39.025,2.025 39.654,2.654 43.766,2.654 44.87,1.55 52.475,1.55 v1(52.625,1.7) ; CN8.13@49.53,67.31 v1@52.32,67.31
PB15: CN8.12 R5.2 R6.2 U3.37 | length 137.3
  Top Layer w0.12: U3.37@24.089,92.654 24.089,93.813 27.93,97.654 34.225,97.654 40.875,91.004 40.875,90.07 46.097,84.848 46.097,81.565 47.337,80.325 47.337,76.184 48.001,75.52 48.001,73.449 48.333,73.117 48.333,71.047 CN8.12@49.53,69.85 ; R5.2@35.175,1.575 R6.2@37.025,1.575 37.725,1.575 v1(38.625,2.475) ; v1(51.925,69.85) 51.751,69.676 51.751,58.174 52.45,57.475 52.45,53.386 51.637,52.573 51.637,42.937 50.875,42.175 50.875,25.872 52.515,24.232 52.515,4.04 52.112,3.637 52.112,2.613 v1(52.375,2.35)
  Bottom Layer w0.12: v1(38.625,2.475) 39.136,2.986 43.903,2.986 45.007,1.882 51.907,1.882 v1(52.375,2.35) ; CN8.12@49.53,69.85 v1(51.925,69.85)
PC0: CN9.28 R2.1 U3.8 | length 104.8
  Top Layer w0.12: CN9.28@6.35,29.21 8.543,31.403 8.543,39.684 8.875,40.016 8.875,42.087 9.542,42.754 9.542,46.895 9.924,47.277 9.924,49.348 10.203,49.627 10.203,51.697 10.535,52.029 10.535,54.1 10.867,54.432 10.867,56.502 11.199,56.834 11.199,58.9 11.531,59.232 11.531,61.307 11.863,61.639 11.863,63.709 12.29,64.137 12.29,66.207 12.527,66.444 12.527,68.515 12.939,68.927 12.939,70.997 13.191,71.249 13.191,73.32 14.436,74.565 19.054,74.565 20.043,75.554 22.712,75.554 23.046,75.888 23.046,78.796 22.089,79.753 U3.8@22.089,80.854 ; R2.1@21.375,1.575 v1(21.375,2.525)
  Bottom Layer w0.12: CN9.28@6.35,29.21 10.432,25.128 10.432,2.413 11.366,1.479 20.976,1.479 21.375,1.878 v1(21.375,2.525)
PC1: CN9.29 R8.2 U3.9 | length 127
  Top Layer w0.12: CN9.29@6.35,26.505 CN9.29@6.35,26.67 6.35,27.517 7.575,28.742 7.575,29.965 8.875,31.265 8.875,39.547 9.207,39.879 9.207,41.95 9.874,42.617 9.874,46.758 10.256,47.14 10.256,49.21 10.535,49.489 10.535,51.56 10.867,51.892 10.867,53.962 11.199,54.294 11.199,56.365 11.531,56.697 11.531,58.762 11.863,59.094 11.863,61.17 12.195,61.502 12.195,63.572 12.622,63.999 12.622,66.07 12.859,66.307 12.859,68.377 13.271,68.789 13.271,70.86 13.523,71.112 13.523,73.182 14.574,74.233 19.192,74.233 20.181,75.222 22.849,75.222 23.378,75.751 23.378,78.934 22.589,79.723 U3.9@22.589,80.854 ; R8.2@42.25,1.575 42.275,1.55 v1(43.375,1.55)
  Bottom Layer w0.12: CN9.29@6.35,26.67 10.1,22.92 10.1,2.276 11.229,1.147 42.997,1.147 43.375,1.525 v1(43.375,1.55)
PC2: CN9.31 SB33.2 U3.10 | length 78.7
  Top Layer w0.12: CN9.31@6.35,21.59 7.55,22.79 7.55,25.708 7.879,26.037 7.879,28.107 8.239,28.467 8.239,29.69 9.539,30.99 9.539,39.272 10.17,39.902 10.17,41.194 10.538,41.563 10.538,46.483 10.92,46.865 10.92,48.935 11.199,49.214 11.199,51.285 11.531,51.617 11.531,53.687 11.863,54.019 11.863,56.09 12.195,56.422 12.195,58.487 12.527,58.819 12.527,60.895 12.859,61.227 12.859,63.297 13.286,63.724 13.286,65.795 13.523,66.032 13.523,68.102 13.935,68.514 13.935,70.585 14.187,70.837 14.187,72.907 14.849,73.569 19.467,73.569 20.456,74.558 23.658,74.558 v1(24.175,75.075) ; v1@23.089,79.788 U3.10@23.089,80.854 ; v1@23.201,79.675 v1(23.201,79.704)
  Bottom Layer w0.12: SB33.2@18.825,78.825 20.55,78.825 21.025,78.35 22.525,78.35 23.201,79.026 v1(23.201,79.704) 23.996,79.704 25.225,78.475 25.225,75.65 24.65,75.075 v1(24.175,75.075)
PC3: CN8.31 SB12.2 U3.11 | length 85.3
  Top Layer w0.12: U3.11@23.589,80.854 23.589,79.936 24.439,79.086 SB12.2@24.439,78.204 25.139,77.504 25.139,75.111 25.692,74.558 31.058,74.558 34.1,77.6 34.1,78.705 34.572,79.177 39.564,79.177 41.029,77.712 41.029,73.571 41.693,72.907 41.693,70.837 42.025,70.505 42.025,66.364 42.689,65.7 42.689,63.629 42.925,63.393 42.925,60.45 43.353,60.022 43.353,58.824 43.685,58.492 43.685,56.422 44.017,56.09 44.017,54.019 44.349,53.687 44.349,51.617 44.681,51.285 44.681,49.214 45.013,48.882 45.013,44.741 45.677,44.077 45.677,42.007 46.009,41.675 46.009,39.604 46.341,39.272 46.341,26.849 48.333,24.857 48.333,22.787 CN8.31@49.53,21.59
PC4: CN8.22 SB2.2 U3.22 | length 96.9
  Top Layer w0.12: SB2.2@12.35,43.85 11.55,43.85 11.325,43.625 11.325,42.4 11.597,42.128 23.303,42.128 23.854,42.679 42.888,42.679 44.534,44.325 v1(44.7,44.325) ; U3.22@28.239,85.504 29.275,85.504 32.614,82.165 40.802,82.165 44.017,78.95 44.017,74.809 44.681,74.145 44.681,72.074 45.013,71.742 45.013,67.601 45.677,66.937 45.677,64.867 46.009,64.535 46.009,62.464 46.341,62.132 46.341,60.062 46.673,59.73 46.673,57.659 47.005,57.327 47.005,55.257 47.337,54.925 47.337,52.854 47.669,52.522 47.669,50.452 48.001,50.12 48.001,45.979 CN8.22@49.53,44.45
  Bottom Layer w0.12: v1(44.7,44.325) 49.405,44.325 CN8.22@49.53,44.45
PC5: CN8.21 SB6.1 U3.23 | length 106
  Top Layer w0.12: SB6.1@12.45,48.475 11.55,48.475 11.252,48.177 11.252,46.727 10.87,46.345 10.87,42.385 11.459,41.796 23.441,41.796 23.992,42.347 43.397,42.347 v1(44.65,43.6) ; U3.23@28.239,86.004 29.244,86.004 32.751,82.497 40.939,82.497 44.349,79.087 44.349,74.946 45.013,74.282 45.013,72.212 45.345,71.88 45.345,67.739 46.009,67.075 46.009,65.004 46.341,64.672 46.341,62.602 46.673,62.27 46.673,60.199 47.005,59.867 47.005,57.797 47.337,57.465 47.337,55.394 47.669,55.062 47.669,52.992 48.001,52.66 48.001,50.589 48.333,50.257 48.333,48.187 CN8.21@49.53,46.99 50.85,45.67 v1(50.85,43.175)
  Bottom Layer w0.12: v1(44.65,43.6) 48.4,43.6 48.825,43.175 v1(50.85,43.175)
PC6: CN8.11 R65.1 U3.38 | length 103
  Top Layer w0.12: U3.38@23.589,92.654 23.589,93.782 27.793,97.986 34.363,97.986 41.232,91.117 41.232,90.182 46.429,84.985 46.429,81.702 47.669,80.462 47.669,76.321 48.333,75.657 48.333,73.587 CN8.11@49.53,72.39 ; R65.1@25.65,45.05 25.65,44.35 26.325,43.675 42.475,43.675 43.763,44.963 43.763,48.723 43.3,49.186 43.3,51.35 42.975,51.675 v1(42.975,52.975) ; v1(50.85,53.375) 50.85,55.1 51.419,55.669 51.419,72.144 v1(51.65,72.375)
  Bottom Layer w0.12: v1(42.975,52.975) 43.375,53.375 v1(50.85,53.375) ; CN8.11@49.53,72.39 49.545,72.375 v1(51.65,72.375)
PC7: CN8.10 R97.1 U3.39 | length 48.5
  Top Layer w0.12: U3.39@23.089,92.654 23.089,93.752 27.655,98.318 31.318,98.318 31.525,98.525 31.732,98.318 34.5,98.318 41.688,91.13 41.968,91.13 42.205,90.893 42.205,89.679 46.761,85.123 46.761,81.84 48.001,80.6 48.001,76.459 CN8.10@49.53,74.93 ; R97.1@29.75,101.65 29.75,100.85 30.25,100.35 v1(30.75,100.35)
  Bottom Layer w0.12: v1(30.75,100.35) 31.525,99.575 v1(31.525,98.55)
PC8: CN8.9 R72.1 U3.40 | length 79.1
  Top Layer w0.12: U3.40@22.589,92.654 22.589,93.721 27.518,98.65 30.875,98.65 31.225,99 31.775,99 32.125,98.65 34.638,98.65 41.095,92.193 42.182,92.193 42.537,91.838 42.537,89.816 47.093,85.26 47.093,81.977 48.333,80.737 48.333,78.667 CN8.9@49.53,77.47 50.727,76.273 50.727,58.538 v1(50.682,58.493) ; R72.1@35.095,58.475 35.25,58.475 35.947,57.778 41.403,57.778 42.175,58.55 v1(42.2,58.525)
  Bottom Layer w0.12: v1(42.2,58.525) 42.232,58.493 v1(50.682,58.493)
PC9: CN8.8 R75.1 U3.41 | length 108.8
  Top Layer w0.12: R75.1@16.8,58.5 16.8,57.825 17.05,57.575 21.525,57.575 22.825,58.875 22.825,60.925 23.475,61.575 33.18,61.575 33.775,60.98 33.775,57.866 34.527,57.114 42.261,57.114 42.475,56.9 v1(42.425,56.9) ; U3.41@22.089,92.654 22.089,93.691 27.38,98.982 30.737,98.982 31.087,99.332 31.913,99.332 32.263,98.982 34.775,98.982 41.232,92.525 42.32,92.525 43.7,91.145 43.7,89.123 47.425,85.398 47.425,82.115 CN8.8@49.53,80.01 51.087,78.453 51.087,56.262 v1(50.65,55.825)
  Bottom Layer w0.12: v1(42.425,56.9) 47.45,56.9 48.475,55.875 50.65,55.875 v1(50.65,55.825)
PC10: CN9.12 SB24.2 U3.52 | length 33.6
  Top Layer w0.12: CN9.12@6.35,69.85 7.627,71.127 7.627,73.198 7.879,73.449 7.879,75.52 8.875,76.516 8.875,82.727 9.207,83.059 9.207,85.125 9.539,85.457 9.539,87.512 9.871,87.844 9.871,92.921 10.15,93.2 12,93.2 12.5,92.7 12.5,91.75 SB24.2@13.2,91.05 13.2,90.85 13.927,90.123 14.435,90.123 15.554,89.004 U3.52@16.439,89.004
PC11: CN9.13 SB23.2 U3.53 | length 32.2
  Top Layer w0.12: CN9.13@6.35,67.31 7.547,68.507 7.547,70.577 7.959,70.99 7.959,73.06 8.211,73.312 8.211,75.382 9.207,76.378 9.207,82.59 9.539,82.922 9.539,84.987 9.871,85.319 9.871,87.375 10.203,87.707 10.203,90.303 SB23.2@10.95,91.05 11.875,90.125 13.455,90.125 13.789,89.791 14.267,89.791 15.476,88.582 16.361,88.582 U3.53@16.439,88.504
PC12: CN9.14 SB20.2 U3.54 | length 33.2
  Top Layer w0.12: CN9.14@6.35,64.77 7.642,66.062 7.642,68.133 7.879,68.369 7.879,70.44 8.291,70.852 8.291,72.923 8.543,73.174 8.543,75.245 9.539,76.241 9.539,82.452 9.871,82.784 9.871,84.85 10.203,85.182 10.203,87.237 10.535,87.569 10.535,89.485 10.843,89.793 12.807,89.793 SB20.2@13.575,89.025 14.5,89.025 15.521,88.004 U3.54@16.439,88.004
PC13: CN9.23 SB5.1 U3.2 | length 51.9
  Top Layer w0.12: CN9.23@6.35,41.91 7.547,43.107 7.547,45.722 v1(7.55,45.725) 7.882,46.057 7.882,47.583 8.264,47.965 8.264,50.035 8.543,50.314 8.543,52.385 8.875,52.717 8.875,54.787 9.207,55.119 9.207,57.19 9.539,57.522 9.539,59.587 9.871,59.919 9.871,61.995 10.203,62.327 10.203,64.397 10.63,64.824 10.63,66.895 10.867,67.132 10.867,69.202 11.279,69.615 11.279,71.685 11.531,71.937 11.531,74.007 13.749,76.225 18.225,76.225 19.089,77.089 U3.2@19.089,80.854 ; v1(11.3,46.15) SB5.1@12.45,46.15
  Bottom Layer w0.12: v1(7.55,45.725) 7.975,46.15 v1(11.3,46.15)
PC14: CN9.24 R58.1 U3.3 | length 66.7
  Top Layer w0.12: CN9.24@6.35,39.37 7.547,40.567 7.547,42.637 8.214,43.304 8.214,47.445 8.596,47.827 8.596,49.898 8.875,50.177 8.875,52.247 9.207,52.579 9.207,54.65 9.539,54.982 9.539,57.052 9.871,57.384 9.871,59.45 10.203,59.782 10.203,61.857 10.535,62.189 10.535,64.259 10.962,64.687 10.962,66.758 11.199,66.994 11.199,69.065 11.611,69.477 11.611,71.548 11.863,71.799 11.863,73.87 13.886,75.893 18.363,75.893 19.421,76.951 19.421,79.636 19.589,79.804 U3.3@19.589,80.854 ; v1(10.85,40.7) 11.057,40.907 19.022,40.907 19.704,40.225 19.704,38.896 R58.1@20.8,37.8
  Bottom Layer w0.12: CN9.24@6.35,39.37 9.52,39.37 v1(10.85,40.7)
PC15: CN9.25 R57.1 U3.4 | length 69.8
  Top Layer w0.12: CN9.25@6.35,36.83 7.547,38.027 7.547,40.097 7.687,40.237 7.879,40.429 7.879,42.5 8.546,43.167 8.546,47.308 8.928,47.69 8.928,49.76 9.207,50.039 9.207,52.11 9.539,52.442 9.539,54.512 9.871,54.844 9.871,56.915 10.203,57.247 10.203,59.312 10.535,59.644 10.535,61.72 10.867,62.052 10.867,64.122 11.294,64.549 11.294,66.62 11.531,66.857 11.531,68.927 11.943,69.34 11.943,71.41 12.195,71.662 12.195,73.732 14.024,75.561 18.5,75.561 19.753,76.814 19.753,79.498 20.089,79.834 U3.4@20.089,80.854 ; v1(10.85,40.025) 11.4,40.575 18.885,40.575 19.372,40.088 19.372,38.722 R57.1@18.45,37.8
  Bottom Layer w0.12: CN9.25@6.35,36.83 8.558,39.038 9.863,39.038 v1(10.85,40.025)
PD2: CN9.15 SB19.1 U3.55 | length 32.9
  Top Layer w0.12: CN9.15@6.35,62.23 7.547,63.427 7.547,65.497 7.7,65.65 ; 7.7,65.65 7.974,65.925 7.974,67.995 8.211,68.232 8.211,70.302 8.623,70.715 8.623,72.785 8.875,73.037 8.875,75.107 9.871,76.103 9.871,82.315 10.203,82.647 10.203,84.712 10.535,85.044 10.535,86.585 10.945,86.995 13.37,86.995 13.475,87.1 SB19.1@13.475,87.675 13.646,87.504 U3.55@16.439,87.504
PF0: CN9.26 SB10.1 | length 51.4
  Top Layer w0.12: CN9.26@6.35,34.29 7.879,35.819 7.879,39.959 8.211,40.291 8.211,42.362 8.878,43.029 8.878,47.17 9.26,47.552 9.26,49.623 9.539,49.902 9.539,51.972 9.871,52.304 9.871,54.375 10.203,54.707 10.203,56.777 10.535,57.109 10.535,59.175 10.867,59.507 10.867,61.582 11.199,61.914 11.199,63.984 11.626,64.412 11.626,66.483 11.863,66.719 11.863,68.79 12.275,69.202 12.275,71.272 12.527,71.524 12.527,73.595 14.161,75.229 18.779,75.229 20.464,76.914 SB10.1@20.464,77.104
PF1: CN9.27 SB11.1 | length 55
  Top Layer w0.12: CN9.27@6.35,31.75 8.211,33.611 8.211,39.822 8.543,40.154 8.543,42.225 9.21,42.892 9.21,47.033 9.592,47.415 9.592,49.485 9.871,49.764 9.871,51.835 10.203,52.167 10.203,54.237 10.535,54.569 10.535,56.64 10.867,56.972 10.867,59.037 11.199,59.369 11.199,61.445 11.531,61.777 11.531,63.847 11.958,64.274 11.958,66.345 12.195,66.582 12.195,68.652 12.607,69.064 12.607,71.135 12.859,71.387 12.859,73.457 14.299,74.897 18.917,74.897 20.02,76 20.95,76 21.814,76.864 SB11.1@21.814,77.104
PLDO_LDO: C51.1 U6.9 U6.11 | length 3.9
  Top Layer w0.3: 15.175,117.975 U6.9@15.175,118.275
  Top Layer w0.4: U6.9@15.175,118.275 14.5,118.275 14.225,118.55 14.225,119.25 14.55,119.575 U6.11@15.175,119.575
  Top Layer w0.65: C51.1@15.175,117.225 15.175,117.975
PROG: C49.2 R99.2 R101.2 R102.2 U6.5 | length 22.4
  Top Layer w0.3: 5.925,110.925 7.075,109.775 12.25,109.775 13.1,110.625 13.1,111.125 13.975,112 R99.2@14.175,112 R102.2@14.175,112.95 ; 5.925,114.05 6.7,114.825 6.7,118.412 8.513,120.225 U6.5@9.625,120.225
  Top Layer w0.65: 5.925,110.925 R101.2@5.925,111.9 C49.2@5.925,113.275 5.925,114.05
RED_LED_K: LD1.2 SB7.2 | length 28.2
  Top Layer w0.45: SB7.2@31.55,50.975 v1@32.3,50.975 ; SB7.2@31.55,50.975 31.925,51.35 v1(32.375,51.35) v1@32.375,51.05 ; SB7.2@31.55,50.975 SB7.2@31.45,50.975 31.525,50.9 v1(32.375,50.9) ; v1@32.3,50.975 v1@32.375,51.05 ; v1@32.3,50.975 v1(32.375,50.9) ; v1(32.375,50.9) v1@32.375,51.05
  Top Layer w0.9: LD1.2@28.1,64.75 LD1.2@28.1,63.875 ; LD1.2@28.1,63.875 v1(27.3,63.075) v1(28.1,63.075) LD1.2@28.1,63.875
  Signal Layer 2 w0.9: v1(27.3,63.075) v1(28.1,63.075) ; v1(32.375,50.9) v1(32.375,51.35)
  Bottom Layer w0.9: 27.55,60.375 27.55,63.075 v1(28.1,63.075) 28.1,60.925 27.55,60.375 ; 27.55,60.375 26.925,59.75 26.925,55.85 31.425,51.35 ; 31.425,51.35 v1(32.375,51.35) v1(32.375,50.9) 31.875,50.9 31.425,51.35
RUN: R109.2 R110.1 U6.4 | length 7.8
  Top Layer w0.3: R109.2@5.8,117.775 5.8,118.325 7.75,120.275 7.75,120.875 ; R110.1@6.05,121.55 7.075,121.55 7.75,120.875 ; U6.4@9.625,120.875 7.75,120.875
STLK_MCO: R130.1 U9.F15 | length 2.7
  Top Layer w0.12: R130.1@33.305,144.55 33.494,144.55 34.707,143.337 35.067,143.337 U9.F15@35.38,143.025
STLK_SWCLK: CN4.2 U9.A14 U13.4 | length 17.9
  Top Layer w0.12: U13.4@24.85,143.8 24.955,143.8 v1(26.025,144.87) 26.498,145.343 29.248,145.343 30.075,144.516 30.648,144.516 31.43,143.734 31.43,143.294 32.13,142.594 U9.A14@32.13,142.375
  Bottom Layer w0.12: v1(26.025,144.87) 26.6,145.445 26.6,147.55 27.15,148.1 29.675,148.1 30.37,148.795 CN4.2@30.37,149.925
STLK_SWDIO: CN4.4 U9.A15 U13.5 | length 14
  Top Layer w0.12: U13.5@24.555,145.1 24.955,145.1 25.53,145.675 v1(26.03,145.675) 29.385,145.675 30.212,144.848 30.785,144.848 31.762,143.871 31.762,143.301 32.038,143.025 U9.A15@32.13,143.025
  Bottom Layer w0.12: CN4.4@25.29,149.925 26.268,148.947 26.268,145.913 v1(26.03,145.675)
STLK_VCP_RX: SW1.13 U9.C10 | length 16
  Top Layer w0.12: v1(26.325,134.04) SW1.13@27.86,134.04 SW1.13@27.89,134.04 ; v1(27.88,140.7) 28.284,141.104 30.68,141.104 31.78,140.004 31.78,139.675 31.985,139.47 32.906,139.47 33.211,139.775 U9.C10@33.43,139.775
  Bottom Layer w0.12: v1(26.325,134.04) 25.85,134.515 25.85,136.78 27.503,138.433 27.503,140.323 v1(27.88,140.7)
STLK_VCP_TX: SW1.12 U9.A7 | length 9
  Top Layer w0.12: v1(26.325,135.31) SW1.12@27.86,135.31 SW1.12@27.915,135.31 ; v1(29.055,138.125) 29.328,137.852 32.13,137.852 U9.A7@32.13,137.825
  Bottom Layer w0.12: v1(26.325,135.31) 26.325,135.82 28.63,138.125 v1(29.055,138.125)
SW1: C58.2 L8.1 U6.15 | length 3.2
  Top Layer w0.3: 16.2,122.175 16.65,122.625 16.65,123.95 C58.2@16.525,124.075
  Top Layer w0.4: U6.15@15.175,122.175 16.2,122.175
SW2: C57.2 L8.2 U6.2 | length 3.2
  Top Layer w0.3: C57.2@8.275,124.075 8.15,123.95 8.15,122.625 8.6,122.175
  Top Layer w0.4: 8.6,122.175 U6.2@9.625,122.175
T_JTDI: CN1.10 SB28.1 U8.1 | length 55.8
  Top Layer w0.12: SB28.1@11,96.725 v1(11,97.9) ; v1(11.406,100.927) 15.802,100.927 v1(15.925,101.05) ; U8.1@28.875,124.032 v1(30.062,124.032) ; v1(30.605,127.724) 31.551,127.724 34.905,124.37 CN1.10@34.905,121.557
  Bottom Layer w0.12: v1(11,97.9) 11,100.488 11.439,100.927 v1(11.406,100.927) ; v1(15.925,101.05) 15.925,101.35 16.785,102.21 18.56,102.21 21.91,105.56 26.335,105.56 30.58,109.805 30.58,116.945 29.68,117.845 29.68,123.65 v1(30.062,124.032) 30.605,124.575 v1@30.605,127.724
T_NRST: C16.2 CN1.12 CN9.30 CN10.10 R67.1 R115.2 U2.1 U3.7 U7.1 | length 172.8
  Top Layer w0.12: CN9.30@6.35,24.13 6.35,24.977 7.547,26.174 7.547,28.245 7.907,28.605 7.907,29.828 9.207,31.128 9.207,39.409 9.838,40.04 v1(9.838,41.638) 10.206,42.006 10.206,46.62 10.588,47.002 10.588,49.073 10.867,49.352 10.867,51.422 11.199,51.754 11.199,53.825 11.531,54.157 11.531,56.227 11.863,56.559 11.863,58.625 12.195,58.957 12.195,61.032 12.527,61.364 12.527,63.434 12.954,63.861 12.954,65.932 13.191,66.169 13.191,68.24 13.603,68.652 13.603,70.722 13.855,70.974 13.855,73.045 14.711,73.901 19.329,73.901 20.318,74.89 23.15,74.89 v1(23.289,75.029) ; v1(11.013,41.638) 11.186,41.464 23.578,41.464 24.129,42.015 34.61,42.015 v1(34.7,41.925) ; U3.7@21.589,80.854 21.589,79.536 21.725,79.4 v1(21.725,79.375) 21.998,79.375 22.714,78.659 22.714,76.214 22.525,76.025 v1(22.525,76.05) ; v1(34.7,44.875) C16.2@34.7,48.05 34.713,48.063 U2.1@35.575,48.063 R67.1@35.575,47.175 ; CN1.12@36.175,121.557 36.175,123.673 U7.1@36.173,123.675 36.173,124.63 R115.2@36.175,124.632 36.175,124.845 36.275,124.845 36.947,125.517 41.507,125.517 v1(42.355,126.365)
  Bottom Layer w0.12: v1(9.838,41.638) v1(11.013,41.638) ; v1(21.725,79.375) 21.725,79.767 24.875,82.917 24.875,87.975 24.025,88.825 24.025,89.98 24.707,90.662 24.707,95.137 26.863,97.293 32.318,97.293 35.182,100.157 35.182,106.482 39.4,110.7 39.4,117.24 41.75,119.59 41.75,120.67 42.355,121.275 v1(42.355,126.365) CN10.10@43.36,126.365 ; v1(22.525,76.05) 22.525,75.793 v1(23.289,75.029) ; v1(34.7,41.925) v1(34.7,44.875)
T_NRSTa: JP7.1 U9.P3 | length 13.7
  Top Layer w0.12: U9.P3@40.58,135.225 40.905,135.55 41.703,135.55 41.953,135.3 v1(44.405,135.3) ; v1(44.405,130.825) 44.42,130.81 JP7.1@49.525,130.81
  Bottom Layer w0.12: v1(44.405,130.825) v1(44.405,135.3)
T_PWR_EN: R122.1 U9.R5 U10.4 | length 7.4
  Top Layer w0.2: U9.R5@41.23,136.525 41.23,136.5 42.305,136.5 42.85,135.955 43.96,135.955 45.28,137.275 R122.1@46.155,137.275 46.955,137.275 47.305,136.925 U10.4@47.705,136.925
T_PWR_EXT: SW1.9 U9.R4 | length 42.3
  Top Layer w0.2: v1(25.83,139.125) 25.805,139.15 SW1.9@27.9,139.15 ; v1(26.305,128.875) 31.775,128.875 33.9,126.75 39.965,126.75 41.49,128.275 42.347,128.275 43.047,128.975 v1(43.555,128.975) ; U9.R4@41.23,135.875 v1(42.205,135.875)
  Bottom Layer w0.2: v1(25.83,139.125) 25.23,139.125 23.734,137.629 23.734,131.421 26.33,128.825 26.355,128.825 v1(26.305,128.875) ; v1(42.205,135.875) 42.225,135.855 42.225,133.58 43.555,132.25 v1(43.555,128.975)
